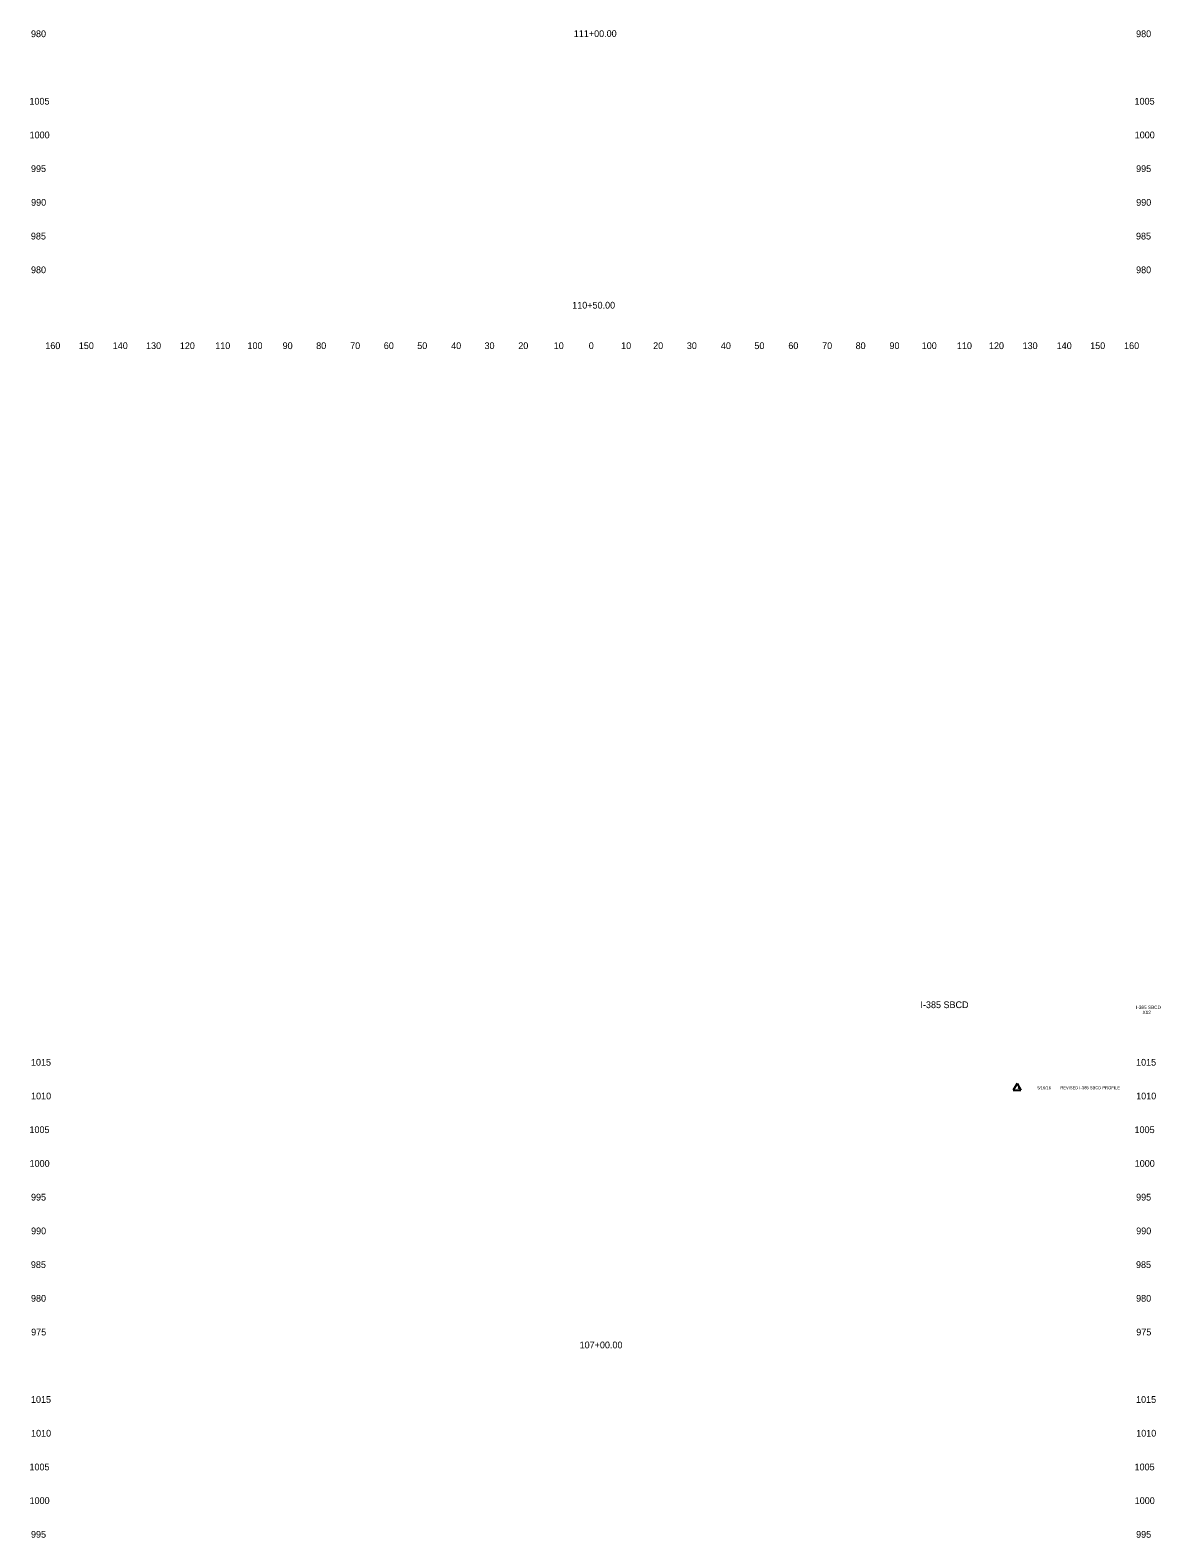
# Model space of a CAD drawing. Extents: x 4994 to 6876, y 4997 to 8804.
# Drawn here: x 5508.6 to 5843.7, y 5445 to 5892.1 of the extents above; entities that cross this region are included whole.
import ezdxf

# ---------------------------------------------------------------- set-up
doc = ezdxf.new("R2010")
doc.units = 0
for name, color, linetype in [('RD_SHT_ID', 7, 'Continuous'), ('RD_SHT_TX', 7, 'Continuous'), ('RD_XS_TX_Offset', 7, 'Continuous'), ('RD_XS_TX_Station', 7, 'Continuous')]:
    doc.layers.add(name, color=color, linetype=linetype)

msp = doc.modelspace()

# ---------------------------------------------------------------- linework, layer by layer
at = {"layer": 'RD_SHT_TX'}
for p, q in [((5801.37, 5579.75), (5800.23, 5577.72)), ((5800.23, 5577.72), (5802.51, 5577.72)), ((5801.37, 5579.75), (5802.51, 5577.72))]:
    msp.add_line(p, q, dxfattribs=at)

# ---------------------------------------------------------------- texts
at = {"layer": 'RD_SHT_ID'}
for s, height, p in [('I-385 SBCD', 2, (5772.69, 5602.06)), ('I-385 SBCD', 1, (5836.63, 5601.8)), ('X12', 1, (5838.57, 5600.3))]:
    msp.add_text(s, height=height, dxfattribs=at).set_placement(p)
at = {"layer": 'RD_SHT_TX'}
for s, p in [('1', (5801.37, 5578.05)), ('5/16/16', (5807.34, 5578.01)), ('REVISED I-385 SBCD PROFILE', (5814.17, 5578.01))]:
    msp.add_text(s, height=0.88, dxfattribs=at).set_placement(p)
at = {"layer": 'RD_XS_TX_Offset'}
for s, p in [('980', (5508.86, 5890)), ('980', (5836.66, 5890)), ('1005', (5508.4, 5870)), ('1005', (5836.2, 5870)), ('1000', (5508.44, 5860)), ('1000', (5836.24, 5860)), ('995', (5508.86, 5850)), ('995', (5836.66, 5850)), ('990', (5508.89, 5840)), ('990', (5836.69, 5840)), ('985', (5508.83, 5830)), ('985', (5836.63, 5830)), ('980', (5508.86, 5820)), ('980', (5836.66, 5820)), ('160', (5513.1, 5797.5)), ('150', (5523.04, 5797.5)), ('140', (5533.1, 5797.5)), ('130', (5542.99, 5797.5)), ('120', (5553.01, 5797.5)), ('110', (5563.51, 5797.5)), ('100', (5573.07, 5797.5)), ('90', (5583.5, 5797.5)), ('80', (5593.46, 5797.5)), ('70', (5603.54, 5797.5)), ('60', (5613.5, 5797.5)), ('50', (5623.43, 5797.5)), ('40', (5633.5, 5797.5)), ('30', (5643.39, 5797.5)), ('20', (5653.4, 5797.5)), ('10', (5663.91, 5797.5)), ('0', (5674.3, 5797.5)), ('0', (5674.3, 5797.5)), ('10', (5683.91, 5797.5)), ('20', (5693.4, 5797.5)), ('30', (5703.39, 5797.5)), ('40', (5713.5, 5797.5)), ('50', (5723.43, 5797.5)), ('60', (5733.5, 5797.5)), ('70', (5743.54, 5797.5)), ('80', (5753.46, 5797.5)), ('90', (5763.5, 5797.5)), ('100', (5773.07, 5797.5)), ('110', (5783.51, 5797.5)), ('120', (5793.01, 5797.5)), ('130', (5802.99, 5797.5)), ('140', (5813.1, 5797.5)), ('150', (5823.04, 5797.5)), ('160', (5833.1, 5797.5)), ('1015', (5508.85, 5585)), ('1015', (5836.65, 5585)), ('1010', (5508.88, 5575)), ('1010', (5836.68, 5575)), ('1005', (5508.4, 5565)), ('1005', (5836.2, 5565)), ('1000', (5508.44, 5555)), ('1000', (5836.24, 5555)), ('995', (5508.86, 5545)), ('995', (5836.66, 5545)), ('990', (5508.89, 5535)), ('990', (5836.69, 5535)), ('985', (5508.83, 5525)), ('985', (5836.63, 5525)), ('980', (5508.86, 5515)), ('980', (5836.66, 5515)), ('975', (5508.91, 5505)), ('975', (5836.71, 5505)), ('1015', (5508.85, 5485)), ('1015', (5836.65, 5485)), ('1010', (5508.88, 5475)), ('1010', (5836.68, 5475)), ('1005', (5508.4, 5465)), ('1005', (5836.2, 5465)), ('1000', (5508.44, 5455)), ('1000', (5836.24, 5455)), ('995', (5508.86, 5445)), ('995', (5836.66, 5445))]:
    msp.add_text(s, height=2, dxfattribs=at).set_placement(p)
at = {"layer": 'RD_XS_TX_Station'}
for s, p in [('111+00.00', (5669.87, 5890.05)), ('110+50.00', (5669.4, 5809.51)), ('107+00.00', (5671.59, 5501.18))]:
    msp.add_text(s, height=2, dxfattribs=at).set_placement(p)

doc.saveas('drawing.dxf')
